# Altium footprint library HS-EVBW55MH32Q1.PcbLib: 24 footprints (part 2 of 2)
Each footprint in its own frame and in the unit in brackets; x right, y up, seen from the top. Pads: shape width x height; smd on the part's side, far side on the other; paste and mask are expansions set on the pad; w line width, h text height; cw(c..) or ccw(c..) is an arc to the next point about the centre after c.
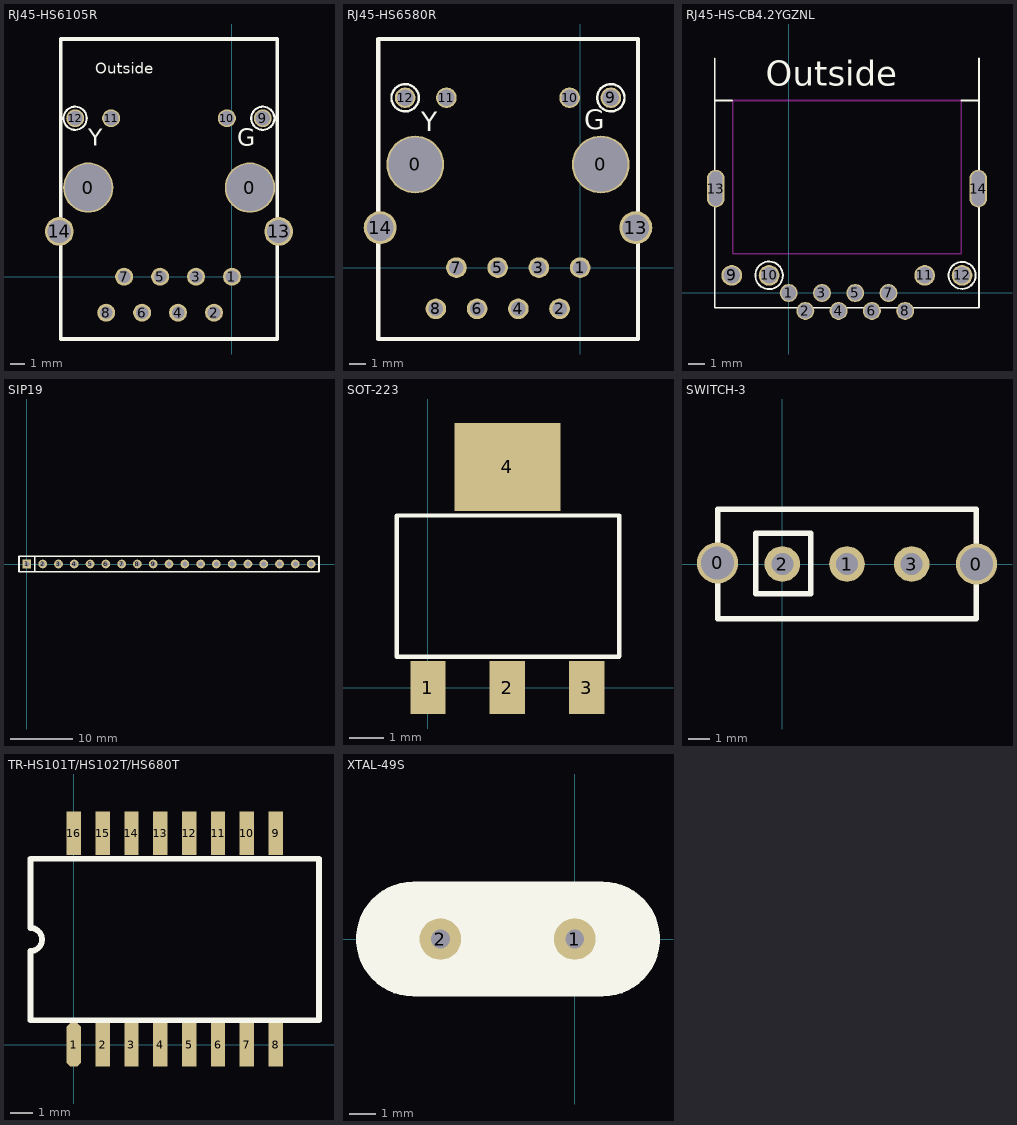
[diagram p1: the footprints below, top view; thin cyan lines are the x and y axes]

## RJ45-HS6105R [mil]
height 537.8
pads (16):
  round 140 hole 130: 0(-400,248.03) 0(50,248.03)
  round 50 hole 35: 1(0,0) 2(-50,-100) 3(-100,0) 4(-150,-100) 5(-200,0) 6(-250,-100) 7(-300,0) 8(-350,-100)
  round 50 hole 40: 9(85.83,440.94) 10(-14.17,440.94) 11(-336.22,440.94) 12(-436.22,440.94)
  round 80 hole 64: 13(129.92,125.98)
  round 80 hole 65: 14(-480.31,125.98)
Top Overlay:
  circle w5.91: c85.83,440.94 r32.28
  circle w5.91: c-436.22,440.94 r32.28
  lines w10: -476.38,-173.23 125.98,-173.23 125.98,661.42 -476.38,661.42 -476.38,-173.23
  text "Outside" at -380,565 h30
  text "G" at 15,365 h47.24
  text "Y" at -400,365 h47.24

## RJ45-HS6580R [mil]
height 633.46
pads (16):
  round 140 hole 130: 0(-400,250) 0(50,250)
  round 50 hole 35: 1(0,0) 2(-50,-100) 3(-100,0) 4(-150,-100) 5(-200,0) 6(-250,-100) 7(-300,0) 8(-350,-100)
  round 50 hole 40: 9(74.41,411.81) 10(-25.59,411.81) 11(-324.41,411.81) 12(-424.41,411.81)
  round 80 hole 64: 13(135.04,96.85)
  round 80 hole 65: 14(-485.04,96.85)
Top Overlay:
  circle w5.91: c-424.41,411.81 r33.17
  circle w5.91: c74.41,411.81 r33.17
  lines w10: -489.76,-173.23 -489.76,554.33 140.16,554.33 140.16,-173.23 -489.76,-173.23
  text "G" at 10,335 h47.24
  text "Y" at -385,330 h47.24

## RJ45-HS-CB4.2YGZNL [mm]
height 11.05
pads (14):
  round 1.1 hole 0.9: 1(0,0) 2(1.02,-1.1) 3(2.04,0) 4(3.06,-1.1) 5(4.08,0) 6(5.1,-1.1) 7(6.12,0) 8(7.14,-1.1)
  round 1.27 hole 1: 9(-3.49,1.08) 10(-1.2,1.08) 11(8.34,1.08) 12(10.63,1.08)
  oval 1.1x2.3 hole 0.8 slot 2.1 at 90 deg: 13(-4.47,6.4) 14(11.62,6.4)
Top Overlay:
  circle w0.12: c-1.2,1.08 r0.846
  circle w0.12: c10.63,1.08 r0.827
  lines w0.1: -4.53,11.8 -3.465,11.8 ; -4.53,14.4 -4.53,-0.9 11.67,-0.9 11.67,14.4 ; 10.57,11.8 11.67,11.8
  text "Outside" at -1.397,12.7 h1.52
Keep-Out Layer:
  lines w0.1: -3.43,2.4 -3.43,11.8 10.57,11.8 10.57,2.4 -3.43,2.4

## SIP19 [mil]
height 43.31
pads (19):
  rect 55x55 hole 32: 1(0,0)
  round 55 hole 32: 2(100,0) 3(200,0) 4(300,0) 5(400,0) 6(500,0) 7(600,0) 8(700,0) 9(800,0) 10(900,0) 11(1000,0) 12(1100,0) 13(1200,0) 14(1300,0) 15(1400,0) 16(1500,0) 17(1600,0) 18(1700,0) 19(1800,0)
Top Overlay:
  lines w10: 50,-50 50,50 ; -50,-50 -50,50 1850,50 1850,-50 -50,-50

## SOT-223 [mil]
height 43.31
pads (4):
  rect 40x60 smd: 1(0,0) 2(90,0) 3(180,0)
  rect 120x100 smd: 4(90,250)
Top Overlay:
  lines w5: -35.43,35 216.54,35 216.97,35.43 216.97,195 -35,195 -35.43,194.57 -35.43,35

## SWITCH-3 [mil]
height 21.65
pads (5):
  round 75 hole 60: 0(-118,2) 0(354,0)
  round 65 hole 40: 1(118,0) 2(0,0) 3(236,0)
Top Overlay:
  lines w10: -118,-100 -118,100 354,100 354,-100 -118,-100 ; -48,-54 -48,56 52,56 52,-54 -48,-54

## TR-HS101T/HS102T/HS680T [mm]
pads (16):
  oct 0.635x1.905 smd: 1(0,0)
  rect 0.635x1.905 smd: 2(1.27,0) 3(2.54,0) 4(3.81,0) 5(5.08,0) 6(6.35,0) 7(7.62,0) 8(8.89,0) 9(8.89,9.3) 10(7.62,9.3) 11(6.35,9.3) 12(5.08,9.3) 13(3.81,9.3) 14(2.54,9.3) 15(1.27,9.3) 16(0,9.3)
Top Overlay:
  lines w0.254: -1.905,1.07 10.795,1.07 10.795,8.182 -1.905,8.182 -1.905,5.134 cw(c-1.905,4.626) -1.905,4.118 -1.905,1.07

## XTAL-49S [mil]
pads (2):
  round 62 hole 28: 1(0,0) 2(-200,0)
Top Overlay:
  region: -264.02,74 -280.02,74 -280.02,-73 -264.02,-73
  region: -253.02,79 -273.02,79 -273.02,-78 -253.02,-78
  region: -240.02,80.18 -259.02,80.18 -259.02,-82.5 -240.02,-82.5
  region: 41.34,82.85 -240,82.85 -240,-82.5 41.34,-82.5
  region: 58,81 41.34,81 41.34,-82.68 58,-82.68
  region: 69.98,81 57.98,81 57.98,-78 69.98,-78
  region: 78.98,75 68.98,75 68.98,-75 78.98,-75
  region: 87.98,71 76.98,71 76.98,-70 87.98,-70
  lines w6: -240,-82.68 cw(c-240,0) -240,82.68 41.34,82.68 cw(c41.34,0) 41.34,-82.68 -240,-82.68
  lines w10: -317,-24 -317,23 -311,29 -311,-37 -308,-40 -308,43 -302,49 -302,-46 -298,-50 -298,54 -294,58 -294,-55 -289,-60 -289,57 -290,58 -290,59 -283,66 -283,-61 ; 88,-60 90,-58 90,63 91,63 97,57 97,-54 96,-55 100,-51 100,49 111,38 106,33 106,-43 112,-37 112,-33 112,30 118,24 118,-25 ; -283,-61 -280,-64 -283,-61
